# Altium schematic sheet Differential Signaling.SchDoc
size 431 x 279 mm; Organization: ORGANIZATION; Address1: ADDRESS 1; Address2: ADDRESS 2; Address3: ADDRESS 3; Address4: ADDRESS 4; Revision: -; ENG_APP_DATE: --/--/--; DSN_APP_DATE: --/--/--; CHK_APP_DATE: --/--/--
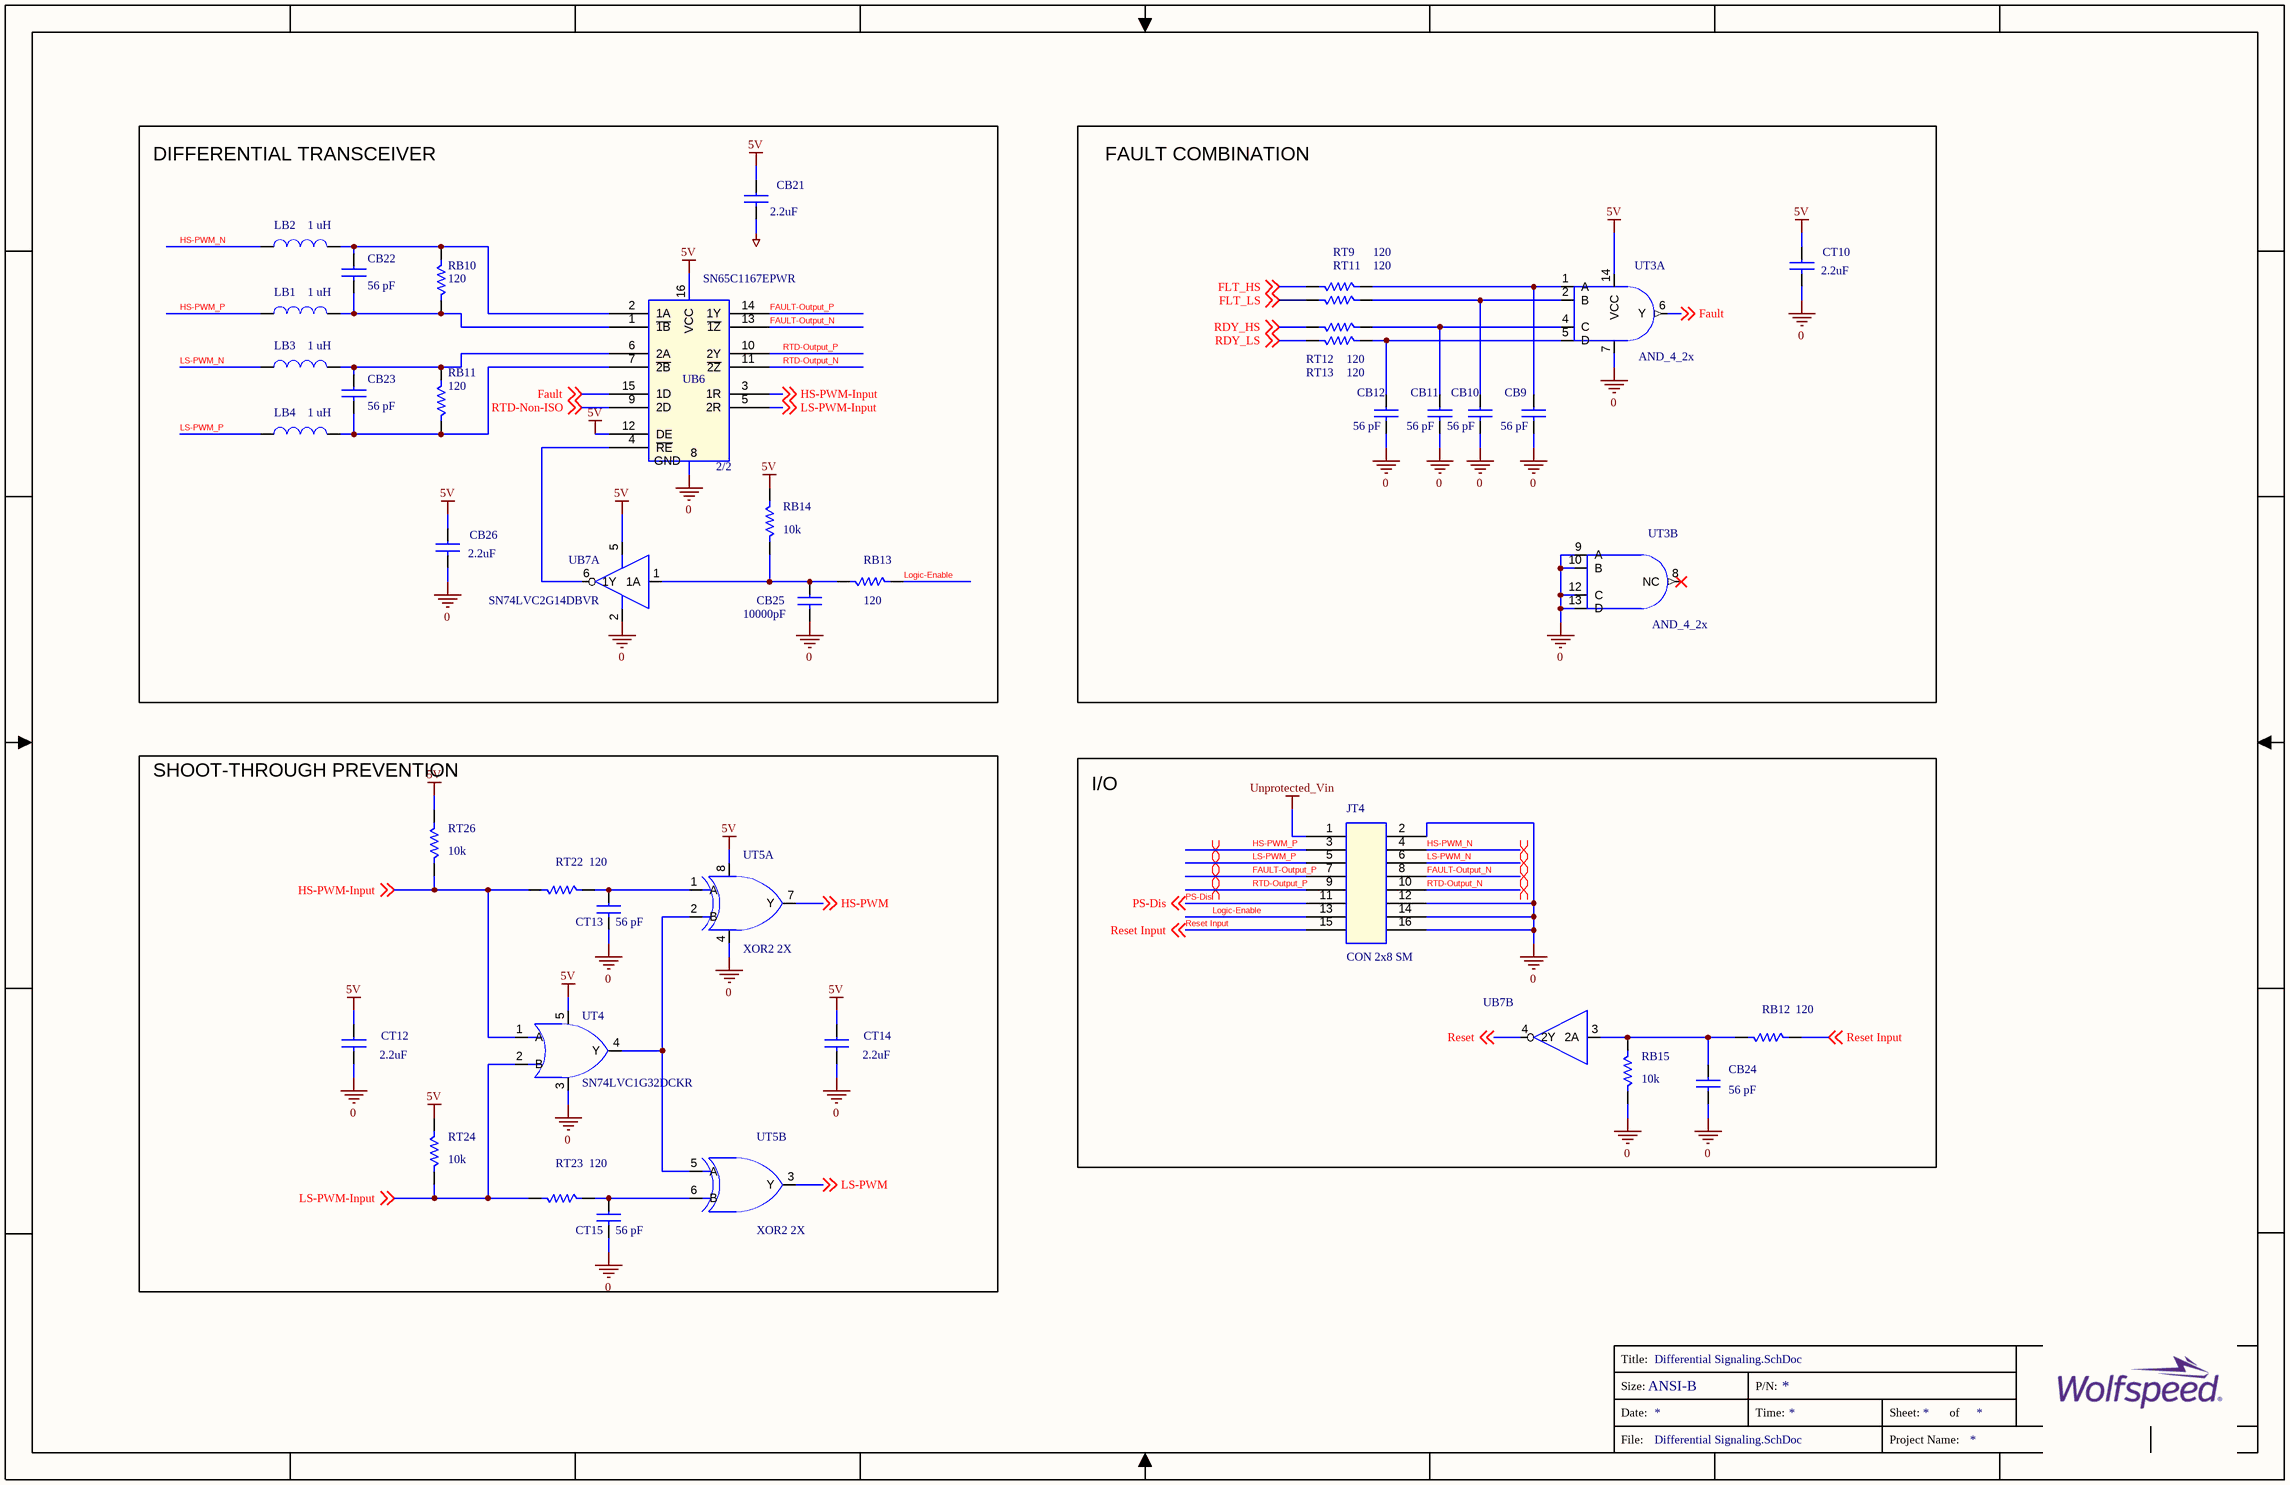
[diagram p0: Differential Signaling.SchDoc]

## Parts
CB9  56 pF  [CAPC1608X90N]
CB10  56 pF  [CAPC1608X90N]
CB11  56 pF  [CAPC1608X90N]
CB12  56 pF  [CAPC1608X90N]
CB21  2.2uF  [CAPC1608X90N]
CB22  56 pF  [CAPC1608X90N]
CB23  56 pF  [CAPC1608X90N]
CB24  56 pF  [CAPC1608X90N]
CB25  10000pF  [CAPC1608X90N]
CB26  2.2uF  [CAPC1608X90N]
CT10  2.2uF  [CAPC1608X90N]
CT12  2.2uF  [CAPC1608X90N]
CT13  56 pF  [CAPC1608X90N]
CT14  2.2uF  [CAPC1608X90N]
CT15  56 pF  [CAPC1608X90N]
JT4  CON 2x8 SM  [CONN16_3020-16-0300-00_CNC]
LB1  1 uH  [INDC1608X95N]
LB2  1 uH  [INDC1608X95N]
LB3  1 uH  [INDC1608X95N]
LB4  1 uH  [INDC1608X95N]
RB10  120  [RESC1608X55N]
RB11  120  [RESC1608X55N]
RB12  120  [RESC1608X55N]
RB13  120  [RESC1608X55N]
RB14  10k  [RESC1608X55N]
RB15  10k  [RESC1608X55N]
RT9  120  [RESC1608X55N]
RT11  120  [RESC1608X55N]
RT12  120  [RESC1608X55N]
RT13  120  [RESC1608X55N]
RT22  120  [RESC1608X55N]
RT23  120  [RESC1608X55N]
RT24  10k  [RESC1608X55N]
RT26  10k  [RESC1608X55N]
UB6  2/2  Manufacturer PN: SN65C1167EPWR  [tssop_16]
UB7  SN74LVC2G14DBVR  [SOT95P280X145-6N_1]  (parts A,B of 2)
UT3  AND_4_2x  [D14]  (parts A,B of 2)
UT4  SN74LVC1G32DCKR  [SOT65P210X110-5N]
UT5  XOR2 2X  [US8_2P40X2P10_ONS]  (parts A,B of 2)

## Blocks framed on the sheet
DIFFERENTIAL TRANSCEIVER: CB21-CB23 CB25 CB26 LB1-LB4 RB10 RB11 RB13 RB14 UB6 UB7
FAULT COMBINATION: CB9-CB12 CT10 RT9 RT11-RT13 UT3
SHOOT-THROUGH PREVENTION: CT12-CT15 RT22-RT24 RT26 UT4 UT5
I/O: CB24 JT4 RB12 RB15 UB7

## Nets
0: CB9.2 CB10.2 CB11.2 CB12.2 CB21.2 CB24.2 CB25.2 CB26.2 CT10.2 CT12.2 CT13.2 CT14.2 CT15.2 JT4.2 JT4.12 JT4.14 JT4.16 RB15.1 UB6.8(GND) UB7.2(GND) UT3.7(GND) UT3.9(A) UT3.10(B) UT3.12(C) UT3.13(D) UT4.3(GND) UT5.4(GND)  [also labelled GND]
5V: CB21.1 CB26.1 CT10.1 CT12.1 CT14.1 RB14.2 RT24.2 RT26.2 UB6.12(DE) UB6.16(VCC) UB7.5(Vcc) UT3.14(VCC) UT4.5(Vcc) UT5.8(VCC)  [also labelled VCC]
Unprotected_Vin: JT4.1
Fault: UB6.15(1D) UT3.6(Y) ; off-sheet Fault
FAULT-Output_N: JT4.8 UB6.13(~{1Z})
FAULT-Output_P: JT4.7 UB6.14(1Y)
FLT_HS: RT9.1 ; off-sheet FLT_HS
FLT_LS: RT11.1 ; off-sheet FLT_LS
HS-PWM: UT5.7(Y) ; off-sheet HS-PWM
HS-PWM-Input: RT22.1 RT26.1 UB6.3(1R) UT4.1(A) ; off-sheet HS-PWM-Input
HS-PWM_N: JT4.4 LB2.1
HS-PWM_P: JT4.3 LB1.1
Logic-Enable: JT4.13 RB13.2
LS-PWM: UT5.3(Y) ; off-sheet LS-PWM
LS-PWM-Input: RT23.1 RT24.1 UB6.5(2R) UT4.2(B) ; off-sheet LS-PWM-Input
LS-PWM_N: JT4.6 LB3.1
LS-PWM_P: JT4.5 LB4.1
PS-Dis: JT4.11 ; off-sheet PS-Dis
RDY_HS: RT12.1 ; off-sheet RDY_HS
RDY_LS: RT13.1 ; off-sheet RDY_LS
Reset: UB7.4(2Y) ; off-sheet Reset
Reset Input: JT4.15 RB12.2 ; off-sheet Reset Input
RTD-Non-ISO: UB6.9(2D) ; off-sheet RTD-Non-ISO
RTD-Output_N: JT4.10 UB6.11(~{2Z})
RTD-Output_P: JT4.9 UB6.10(2Y)
NetCB9_1: CB9.1 RT9.2 UT3.1(A)
NetCB10_1: CB10.1 RT11.2 UT3.2(B)
NetCB11_1: CB11.1 RT12.2 UT3.4(C)
NetCB12_1: CB12.1 RT13.2 UT3.5(D)
NetCB22_1: CB22.1 LB2.2 RB10.2 UB6.2(1A)
NetCB22_2: CB22.2 LB1.2 RB10.1 UB6.1(~{1B})
NetCB23_1: CB23.1 LB3.2 RB11.2 UB6.6(2A)
NetCB23_2: CB23.2 LB4.2 RB11.1 UB6.7(~{2B})
NetCB24_1: CB24.1 RB12.1 RB15.2 UB7.3(2A)
NetCB25_1: CB25.1 RB13.1 RB14.1 UB7.1(1A)
NetCT13_1: CT13.1 RT22.2 UT5.1(A)
NetCT15_1: CT15.1 RT23.2 UT5.6(B)
NetUB6_4: UB6.4(~{RE}) UB7.6(1Y)
NetUT4_4: UT4.4(Y) UT5.2(B) UT5.5(A)

Not connected (* = marked no-connect by the designer): UT3 3(NC2) 8(NC)* 11(NC)

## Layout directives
differential pair: FAULT-Output_N, FAULT-Output_P, HS-PWM_N, HS-PWM_P, LS-PWM_N, LS-PWM_P, RTD-Output_N, RTD-Output_P

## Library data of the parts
CB9 CB10 = CAP_Dup1: CAP CER 56PF 50V C0G/NP0 0603; Manufacturer: Samsung Electro-Mechanics; Manufacturer PN: CL10C560JB8NNNC; Dielectric Type: Capacitors; Temperature Coefficient: C0G, NP0; Tolerance: 5%; CLASS: DISCRETE
CB11 CB12 CB22-CB24 CT13 CT15 = CAP_Dup1: CAP CER 56PF 50V C0G/NP0 0603; Manufacturer PN: CL10C560JB8NNNC; Manufacturer: Samsung Electro-Mechanics; CLASS: DISCRETE; Tolerance: 5%; Temperature Coefficient: C0G, NP0; Dielectric Type: Capacitors
CB21 CT10 CT12 CT14 = CAP_2.2uF: CAP CER 2.2UF 50V X5R 0603; Company Part Status: Obsolete; Manufacturer: Murata Electronics North America; Manufacturer PN: GRT188R61H225ME13D; Tolerance: 20%; CLASS: DISCRETE
CB25 = CAP: CAP CER 10000PF 25V 10% X7R 0603; Manufacturer PN: CL10B103KA8NNNC; Manufacturer: Samsung Electro-Mechanics America, Inc.; PART_NUMBER: TMP-566; Company Part Status: New; CLASS: DISCRETE; Dielectric Type: Capacitors
CB26 = CAP_2.2uF: CAP CER 2.2UF 50V X5R 0603; Manufacturer PN: GRT188R61H225ME13D; Manufacturer: Murata Electronics North America; Company Part Status: Obsolete; CLASS: DISCRETE; Tolerance: 20%
JT4 = CON16A_Corrected: CONN HEADER SMD 16POS 2.54MM; Manufacturer: Sullins Connector Solutions; Manufacturer PN: SBH11-NBPC-D08-SM-BK; Company Part Status: Released; CLASS: IO; PCB Footprint: CON_2x8_shrouded_SM
LB1-LB3 = INDUCTOR: FIXED IND 1UH 600MA 150 MOHM SMD; Manufacturer PN: MLZ1608A1R0WT000; Manufacturer: TDK Corporation; CLASS: DISCRETE; Tolerance: 20%
LB4 = INDUCTOR: FIXED IND 1UH 600MA 150 MOHM SMD; Manufacturer: TDK Corporation; Manufacturer PN: MLZ1608A1R0WT000; Tolerance: 20%; CLASS: DISCRETE
RB10-RB12 RT9 RT11-RT13 = RES_1: RES SMD 120 OHM 1% 1/10W 0603; Manufacturer PN: RC0603FR-07120RL; Manufacturer: Yageo; PART_NUMBER: TMP-957; Company Part Status: Released; CLASS: DISCRETE; Rated Power: 0.1W, 1/10W; Temperature Coefficient: 100ppm/C
RB13 RT22 RT23 = RES_1: RES SMD 120 OHM 1% 1/10W 0603; PART_NUMBER: TMP-957; Manufacturer: Yageo; Manufacturer PN: RC0603FR-07120RL; Company Part Status: Released; Temperature Coefficient: 100ppm/C; Rated Power: 0.1W, 1/10W; CLASS: DISCRETE
RB14 RT26 = RES: RES SMD 10K OHM 1% 1/10W 0603; Manufacturer PN: ERJ-3EKF1002V; Manufacturer: Panasonic Electronic Components; Company Part Status: New; PART_NUMBER: TMP-788; CLASS: DISCRETE; Rated Power: 0.1W, 1/10W; Temperature Coefficient: 100ppm/C
RB15 = RES: RES SMD 10K OHM 1% 1/10W 0603; Manufacturer: Panasonic Electronic Components; Company Part Status: New; PART_NUMBER: TMP-788; CLASS: DISCRETE; Rated Power: 0.1W, 1/10W; Temperature Coefficient: 100ppm/C
RT24 = RES: RES SMD 10K OHM 1% 1/10W 0603; PART_NUMBER: TMP-788; Company Part Status: New; Manufacturer: Panasonic Electronic Components; Manufacturer PN: ERJ-3EKF1002V; Temperature Coefficient: 100ppm/C; Rated Power: 0.1W, 1/10W; CLASS: DISCRETE
UB6 = SN65C1167: IC DIFF DVR/RCVR DUAL 16-TSSOP; Manufacturer: Texas Instruments; Company Part Status: Released; Supply Voltage: 4.5V ~ 5.5V
UB7 = SN74LVC2G04: IC INVERTER DUAL SHMT-T SOT-23-6; PART_NUMBER: TMP-658; Manufacturer: Texas Instruments; PCB Footprint: SOT_23_6; Supply Voltage: 1.65 V - 5.5 V
UT3 = AND4_2X: IC GATE AND 2CH 4-INP 14SOIC; Company Part Status: Released; Manufacturer: Texas Instruments; Manufacturer PN: SN74HC21DR; Supply Voltage: 2 V - 6 V
UT4 = SN74LVC1G32: IC GATE OR 1CH 2-INP SC-70-5; Manufacturer: Texas Instruments; PART_NUMBER: TMP-446; PCB Footprint: SC70_5; Supply Voltage: 1.65 V - 5.5 V
UT5 = XOR2_2X: IC GATE XOR 2CH 2-INP US8; Manufacturer PN: NL27WZ86USG; Manufacturer: ON Semiconductor; Company Part Status: Released; PCB Footprint: US8_2P40X2P10; Supply Voltage: 1.65 V ~ 5.5 V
